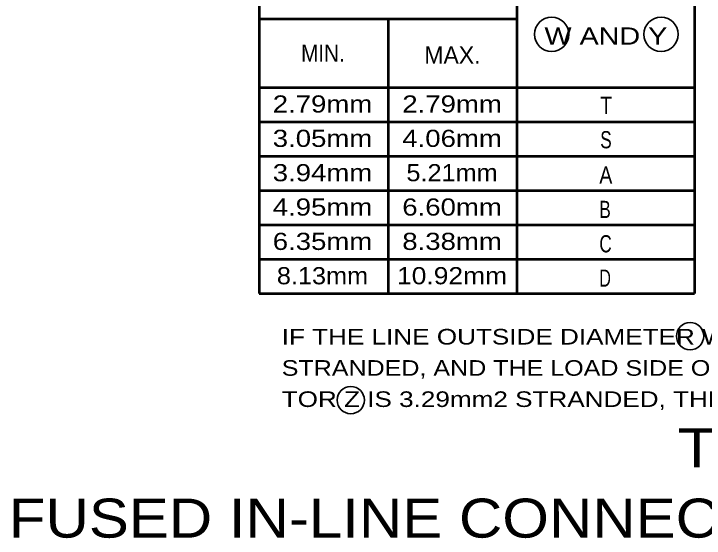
# Model space of a CAD drawing. Extents: x -32 to 824, y -6 to 538.
# Drawn here: x 516.5 to 622.7, y 136.1 to 216.7 of the extents above; entities that cross this region are included whole.
import ezdxf
from ezdxf.enums import TextEntityAlignment as Align

# ---------------------------------------------------------------- set-up
doc = ezdxf.new("R2010")
doc.units = 0
doc.header["$LTSCALE"] = 1.1
doc.layers.add('1', color=7, linetype='Continuous', lineweight=53)

msp = doc.modelspace()

# ---------------------------------------------------------------- linework, layer by layer
at = {"layer": '1'}
for p, q in [((554.287, 226.546), (554.287, 173.746)), ((593.887, 226.546), (593.887, 173.746)), ((554.287, 215.986), (593.887, 215.986)), ((574.087, 215.986), (574.087, 173.746)), ((554.287, 205.426), (621.227, 205.426)), ((554.287, 200.146), (621.227, 200.146)), ((554.287, 194.866), (621.227, 194.866)), ((554.287, 189.586), (621.227, 189.586)), ((554.287, 184.306), (621.227, 184.306)), ((554.287, 179.026), (621.227, 179.026)), ((554.287, 173.746), (621.227, 173.746))]:
    msp.add_line(p, q, dxfattribs=at)
msp.add_lwpolyline([(554.287, 226.546), (621.227, 226.546), (621.227, 173.746)], dxfattribs=at)
at = {"layer": '1', "lineweight": 35}
for centre, radius in [((599.241, 213.585), 2.64), ((616.08, 213.585), 2.64), ((620.538, 167.17), 2.1), ((568.356, 157.353), 2.1)]:
    msp.add_circle(centre, radius, dxfattribs=at)

# ---------------------------------------------------------------- texts
at = {"layer": '1'}
for s, height, width, p in [('W AND Y', 2.64, 1.25, (607.597, 212.004)), ('2.79mm', 2.64, 1.2, (564.015, 201.551)), ('2.79mm', 2.64, 1.2, (583.937, 201.551)), ('3.05mm', 2.64, 1.2, (564.015, 196.271)), ('4.06mm', 2.64, 1.2, (583.937, 196.271)), ('3.94mm', 2.64, 1.2, (564.015, 190.991)), ('5.21mm', 2.64, 1.1, (583.937, 190.991)), ('4.95mm', 2.64, 1.2, (564.015, 185.711)), ('6.60mm', 2.64, 1.2, (583.937, 185.711)), ('6.35mm', 2.64, 1.2, (564.015, 180.431)), ('8.38mm', 2.64, 1.2, (583.937, 180.431)), ('8.13mm', 2.64, 1.1, (564.015, 175.151)), ('10.92mm', 2.64, 1.15, (583.937, 175.151)), ('TYPE 6', 6, 1.2, (635.228, 147)), ('FUSED IN-LINE CONNECTOR KIT FOR JUNCTION BOX', 6, 1.15, (635.228, 136.2))]:
    msp.add_text(s, height=height, dxfattribs=dict(at, width=width)).set_placement(p, align=Align.CENTER)
for s, height, width, p in [('MIN.', 2.64, 0.9, (560.725, 209.357)), ('T', 2.64, 0.85, (606.719, 201.339)), ('S', 2.64, 0.75, (606.719, 196.059)), ('A', 2.64, 0.85, (606.584, 190.622)), ('B', 2.64, 0.75, (606.584, 185.342)), ('C', 2.64, 0.75, (606.584, 180.062)), ('D', 2.64, 0.7, (606.584, 174.782)), ('IF THE LINE OUTSIDE DIAMETER W IS 10.7mm AND THE CONDUCTOR X IS 17.42mm2', 2.4, 1.25, (557.742, 165.888)), ('STRANDED, AND THE LOAD SIDE OUTSIDE DIAMETER Y IS 7.4mm AND THE CONDUC-', 2.4, 1.2, (557.742, 161.088)), ('TOR Z IS 3.29mm2 STRANDED, THE KIT REQUIRED WILL BE VI-D3-C6.', 2.4, 1.25, (557.742, 156.288))]:
    msp.add_text(s, height=height, dxfattribs=dict(at, width=width)).set_placement(p)
msp.add_text('MAX.', height=2.64, dxfattribs=at).set_placement((579.678, 209.07))

doc.saveas('drawing.dxf')
